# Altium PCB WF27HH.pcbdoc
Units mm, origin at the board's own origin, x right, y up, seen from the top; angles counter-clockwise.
Board outline 16.47 x 16.15 mm, 2 copper layers (Top Layer, Bottom Layer); 1 components, 0 nets, 11 pads, 0 vias.
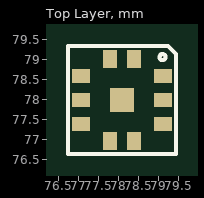
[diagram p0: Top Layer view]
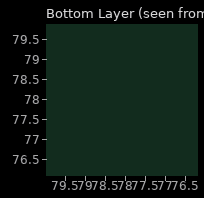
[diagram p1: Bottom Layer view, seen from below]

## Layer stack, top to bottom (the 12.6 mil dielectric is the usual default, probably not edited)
Top Layer: signal copper (thickness not stored)
Dielectric: dielectric 0.32, FR-4, Dk 4.8
Bottom Layer: signal copper (thickness not stored)

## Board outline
86.323,69.85 69.85,69.85 69.85,85.999 86.323,85.999

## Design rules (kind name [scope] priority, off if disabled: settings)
BoardOutlineClearance safeClearance [All] p0: genericclearance=0.254 ignorepadtopadclearanceinfootprint=FALSE except(0: Arc-SplitContinuation Track-SplitContinuation SMDPad-SplitContinuation THPad-SplitContinuation Via-SplitContinuation Fill-SplitContinuation Poly-SplitContinuation Region-SplitContinuation Text-SplitContinuation; 0.152: Track-CutoutEdge SMDPad-CutoutEdge THPad-CutoutEdge Via-CutoutEdge Fill-CutoutEdge Region-CutoutEdge; 0.3: Track-OutlineEdge SMDPad-OutlineEdge THPad-OutlineEdge Via-OutlineEdge Fill-OutlineEdge Region-OutlineEdge Poly-OutlineEdge Text-OutlineEdge)
Clearance safeClearance [All] p1: gap=0.178 ignorepadtopadclearanceinfootprint=FALSE except(0.152: Track-Track Track-SMDPad SMDPad-SMDPad Track-THPad SMDPad-THPad THPad-THPad Track-Via SMDPad-Via THPad-Via Via-Via Track-Fill SMDPad-Fill THPad-Fill Via-Fill Fill-Fill Track-Region SMDPad-Region THPad-Region Via-Region Fill-Region Region-Region Track-Poly SMDPad-Poly THPad-Poly Via-Poly Fill-Poly Region-Poly Poly-Poly Track-Text SMDPad-Text THPad-Text Via-Text Fill-Text Region-Text Poly-Text Text-Text; 0.175: Track-Hole SMDPad-Hole THPad-Hole Via-Hole Fill-Hole Region-Hole Poly-Hole Text-Hole Sheet-Hole; 0.3: Track-Sheet SMDPad-Sheet THPad-Sheet Via-Sheet Fill-Sheet Region-Sheet Poly-Sheet Text-Sheet)
DiffPairsRouting differentialPair [All] p1: maxuncoupledlength=10 minlimit=6 maxlimit=6 mostfreqgap=6 toplayer_minwidth=5 toplayer_prefwidth=10 toplayer_maxwidth=100 bottomlayer_minwidth=5 bottomlayer_prefwidth=10 bottomlayer_maxwidth=100
PasteMaskExpansion pasteMaskExpansion [All] p1: expansion=0
PlaneConnect innerPlane [All] p1: planeconnectstyle=Relief reliefexpansion=0.508 reliefentries=4 reliefconductorwidth=0.254 reliefairgap=0.254
PolygonConnect copperRegion [All] p1: connectstyle=Relief reliefentries=4 reliefconductorwidth=10 polygonreliefangle="90 Angle" airgapwidth=10
RoutingVias viaSize [All] p1: viastyle="Through Hole" holewidth=12.0078 minholewidth=11.811 maxholewidth=236.2204 width=24.0158 minwidth=19.685 maxwidth=393.7008
SolderMaskExpansion solderMaskExpansion [All] p1: useseparateexpansions=TRUE expansion=2 expansionbottom=2
Width trackWidth [All] p1: maxlimit=100 minlimit=5 preferedwidth=10

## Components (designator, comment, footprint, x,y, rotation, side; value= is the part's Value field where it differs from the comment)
? "27hh" 27hh 78.363,78.108 r0 top

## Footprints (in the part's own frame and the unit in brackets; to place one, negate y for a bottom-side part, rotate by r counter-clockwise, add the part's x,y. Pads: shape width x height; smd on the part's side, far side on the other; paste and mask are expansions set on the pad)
27hh [mm]
  rect 0.35x0.45 smd: 1(0.03,0.906) 2(-0.57,0.906) 6(-0.57,-1.144) 7(0.03,-1.144)
  rect 0.45x0.35 smd: 3(-1.295,0.481) 4(-1.295,-0.119) 5(-1.295,-0.719) 8(0.755,-0.719) 9(0.755,-0.119) 10(0.755,0.481)
  rect 0.6x0.6 smd: 11(-0.27,-0.119)
  silkscreen extent -1.62,-1.47 1.08,1.23

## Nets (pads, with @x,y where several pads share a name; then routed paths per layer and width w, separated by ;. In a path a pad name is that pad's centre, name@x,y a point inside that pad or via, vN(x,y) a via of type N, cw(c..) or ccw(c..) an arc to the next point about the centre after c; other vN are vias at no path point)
pads on no net: ?.1 ?.2 ?.3 ?.4 ?.5 ?.6 ?.7 ?.8 ?.9 ?.10 ?.11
